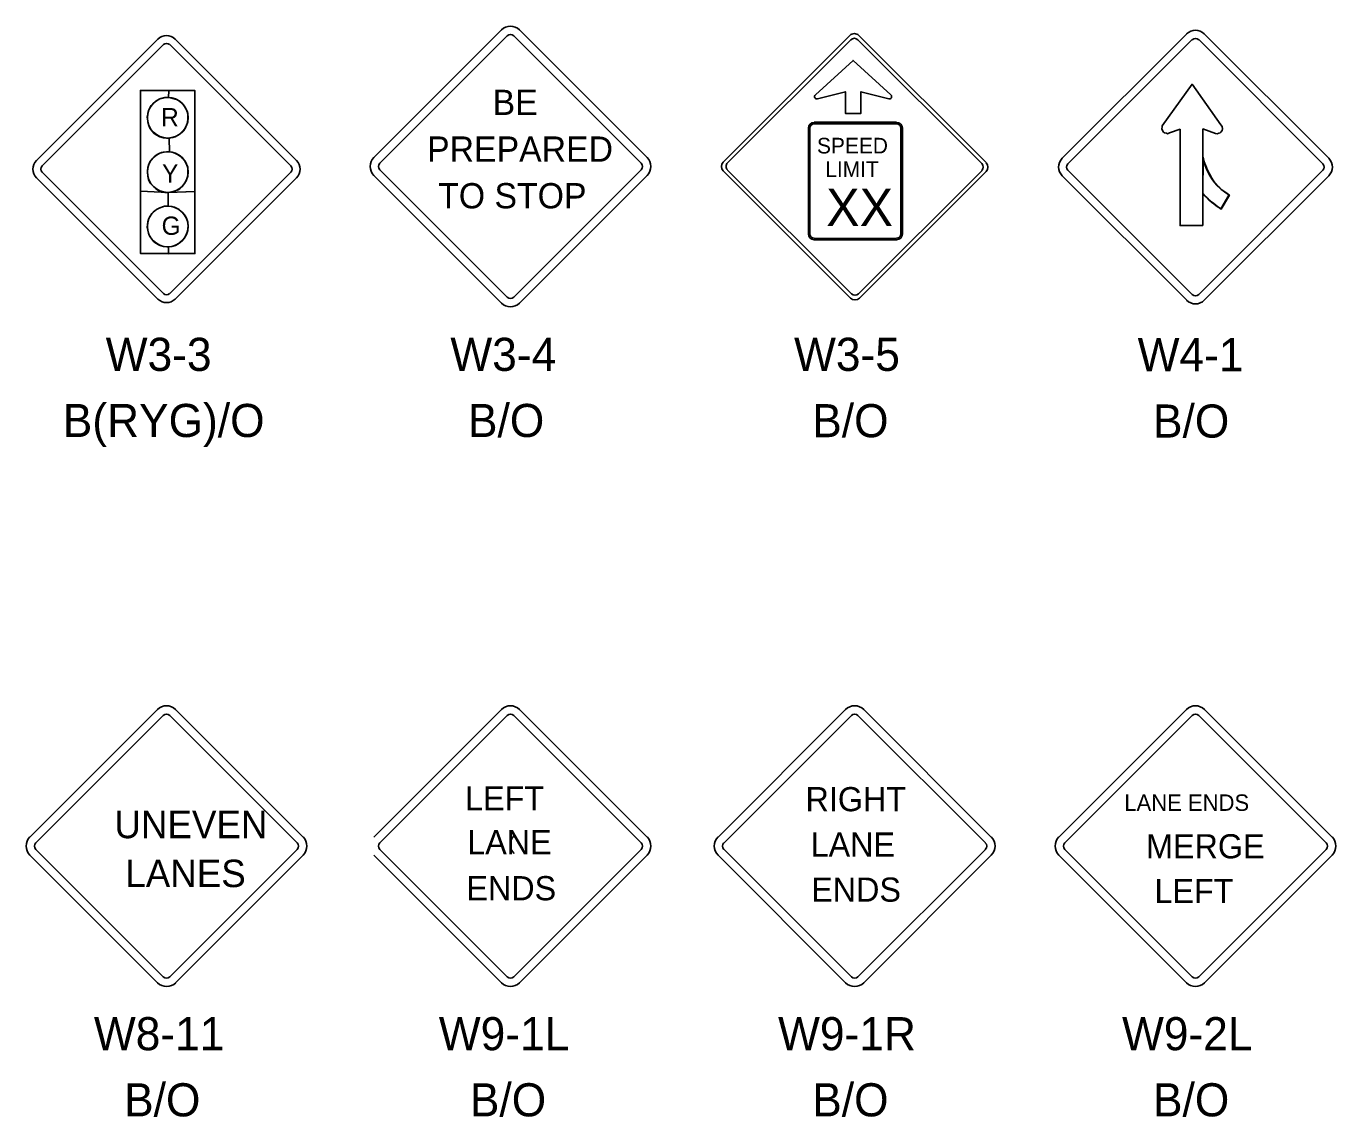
# Model space of a CAD drawing. Extents: x 10034 to 10794, y 10044 to 10499.
# Drawn here: x 10034.9 to 10173.2, y 10279.6 to 10394.8 of the extents above; entities that cross this region are included whole.
import ezdxf

# ---------------------------------------------------------------- set-up
doc = ezdxf.new("R2010")
doc.units = 0
for name, color, linetype in [('DSIndex', 7, 'Continuous'), ('DSText', 7, 'Continuous'), ('DSTitle', 7, 'Continuous'), ('PlotBorder_dp', 7, 'Continuous')]:
    doc.layers.add(name, color=color, linetype=linetype)

msp = doc.modelspace()

# ---------------------------------------------------------------- linework, layer by layer
at = {"layer": 'DSIndex'}
for p, q in [((10071.58, 10380.96), (10085.06, 10394.44)), ((10072.21, 10380.35), (10085.67, 10393.81)), ((10086.37, 10393.81), (10099.82, 10380.35)), ((10086.98, 10394.44), (10100.45, 10380.96)), ((10108.5, 10380.47), (10121.88, 10393.86)), ((10136.27, 10380.41), (10122.82, 10393.86)), ((10144.31, 10380.87), (10157.46, 10394.02)), ((10159.32, 10394.02), (10172.47, 10380.87)), ((10035.94, 10380.64), (10048.77, 10393.47)), ((10036.54, 10380.06), (10049.35, 10392.88)), ((10050.02, 10392.88), (10062.83, 10380.06)), ((10050.6, 10393.47), (10063.42, 10380.64)), ((10108.96, 10380.38), (10121.98, 10393.4)), ((10135.81, 10380.31), (10122.73, 10393.4)), ((10144.92, 10380.28), (10158.05, 10393.41)), ((10158.73, 10393.41), (10171.86, 10380.28)), ((10046.94, 10388.03), (10052.68, 10388.03)), ((10046.94, 10370.8), (10046.94, 10388.03)), ((10052.68, 10388.03), (10052.68, 10370.8)), ((10118.47, 10387.15), (10118.47, 10387.15)), ((10118.47, 10387.15), (10118.47, 10387.15)), ((10118.47, 10387.15), (10118.47, 10387.15)), ((10117.49, 10384.05), (10117.49, 10372.88)), ((10117.65, 10384.05), (10117.65, 10372.88)), ((10126.81, 10384.68), (10118.11, 10384.68)), ((10126.81, 10384.52), (10118.11, 10384.52)), ((10127.27, 10372.88), (10127.27, 10384.05)), ((10127.43, 10372.88), (10127.43, 10384.05)), ((10048.77, 10365.99), (10035.94, 10378.82)), ((10049.35, 10366.59), (10036.54, 10379.4)), ((10062.83, 10379.4), (10050.02, 10366.59)), ((10063.42, 10378.82), (10050.6, 10365.99)), ((10085.06, 10365.57), (10071.58, 10379.05)), ((10085.67, 10366.2), (10072.21, 10379.66)), ((10099.82, 10379.66), (10086.37, 10366.2)), ((10100.45, 10379.05), (10086.98, 10365.57)), ((10121.95, 10366.09), (10108.5, 10379.54)), ((10122.04, 10366.55), (10108.96, 10379.63)), ((10122.79, 10366.55), (10135.81, 10379.56)), ((10122.88, 10366.09), (10136.27, 10379.47)), ((10157.46, 10365.86), (10144.31, 10379.01)), ((10158.05, 10366.47), (10144.92, 10379.6)), ((10171.86, 10379.6), (10158.73, 10366.47)), ((10172.47, 10379.01), (10159.32, 10365.86)), ((10161.08, 10375.54), (10161.93, 10376.96)), ((10118.11, 10372.41), (10126.81, 10372.41)), ((10118.11, 10372.25), (10126.81, 10372.25)), ((10052.68, 10370.8), (10046.94, 10370.8)), ((10035.25, 10309.13), (10048.73, 10322.61)), ((10035.88, 10308.52), (10049.34, 10321.98)), ((10050.03, 10321.98), (10063.49, 10308.52)), ((10050.64, 10322.61), (10064.12, 10309.13)), ((10049.34, 10294.37), (10035.88, 10307.83)), ((10063.49, 10307.83), (10050.03, 10294.37)), ((10048.73, 10293.74), (10035.25, 10307.22)), ((10064.12, 10307.22), (10050.64, 10293.74))]:
    msp.add_line(p, q, dxfattribs=at)
for points in [[(10118.23, 10387.58), (10122.22, 10391.21), (10126.21, 10387.58)], [(10118.23, 10387.58), (10122.22, 10391.21), (10126.21, 10387.58)], [(10118.23, 10387.58), (10122.22, 10391.21), (10126.21, 10387.58)], [(10125.98, 10387.15), (10123.05, 10387.9), (10123.05, 10385.62), (10121.4, 10385.62), (10121.4, 10387.9), (10118.47, 10387.15)], [(10125.98, 10387.15), (10123.05, 10387.9), (10123.05, 10385.62), (10121.4, 10385.62), (10121.4, 10387.9), (10118.47, 10387.15)], [(10125.98, 10387.15), (10123.05, 10387.9), (10123.05, 10385.62), (10121.4, 10385.62), (10121.4, 10387.9), (10118.47, 10387.15)]]:
    msp.add_lwpolyline(points, dxfattribs=at)
for points in [[(10049.92, 10388.04), (10049.88, 10387.31), (10049.69, 10387.31), (10049.49, 10387.28), (10049.29, 10387.21), (10049.09, 10387.18), (10048.89, 10387.11), (10048.72, 10387.01), (10048.56, 10386.91), (10048.46, 10386.81), (10048.29, 10386.71), (10048.19, 10386.58), (10048.06, 10386.45), (10047.96, 10386.28), (10047.86, 10386.08), (10047.76, 10385.92), (10047.73, 10385.72), (10047.69, 10385.55), (10047.63, 10385.25), (10047.66, 10384.99), (10047.73, 10384.62), (10047.83, 10384.35), (10047.93, 10384.06), (10048.12, 10383.79), (10048.36, 10383.49), (10048.66, 10383.33), (10048.99, 10383.13), (10049.35, 10383.03), (10049.69, 10382.99), (10049.95, 10382.99), (10049.98, 10381.57), (10049.69, 10381.57), (10049.42, 10381.53), (10049.15, 10381.47), (10048.89, 10381.37), (10048.69, 10381.27), (10048.46, 10381.1), (10048.23, 10380.9), (10048.09, 10380.7), (10047.93, 10380.5), (10047.83, 10380.2), (10047.69, 10379.91), (10047.66, 10379.51), (10047.69, 10379.01), (10047.79, 10378.58), (10047.96, 10378.25), (10048.23, 10377.95), (10048.56, 10377.65), (10048.82, 10377.45), (10049.19, 10377.32), (10049.52, 10377.25), (10049.82, 10377.25), (10046.93, 10377.38), (10046.93, 10388.04)], [(10049.92, 10388.02), (10049.89, 10387.3), (10050.25, 10387.24), (10050.61, 10387.12), (10050.85, 10387.04), (10051.08, 10386.86), (10051.3, 10386.71), (10051.47, 10386.53), (10051.62, 10386.32), (10051.74, 10386.05), (10051.89, 10385.75), (10051.95, 10385.39), (10051.95, 10385.04), (10051.89, 10384.64), (10051.8, 10384.38), (10051.68, 10384.08), (10051.5, 10383.81), (10051.26, 10383.6), (10051.12, 10383.45), (10050.85, 10383.27), (10050.61, 10383.15), (10050.34, 10383.07), (10050.13, 10383.03), (10049.95, 10383), (10049.98, 10381.57), (10050.28, 10381.51), (10050.55, 10381.42), (10050.76, 10381.3), (10051.03, 10381.15), (10051.26, 10381), (10051.41, 10380.83), (10051.65, 10380.56), (10051.8, 10380.26), (10051.92, 10379.93), (10051.95, 10379.57), (10051.92, 10379.12), (10051.86, 10378.8), (10051.77, 10378.5), (10051.62, 10378.26), (10051.44, 10378.02), (10051.3, 10377.84), (10051.08, 10377.66), (10050.91, 10377.54), (10050.61, 10377.42), (10050.31, 10377.3), (10049.89, 10377.24), (10052.67, 10377.36), (10052.68, 10388.03)], [(10159.17, 10373.78), (10159.17, 10383.97), (10160.51, 10383.49), (10160.67, 10383.46), (10160.85, 10383.51), (10160.98, 10383.55), (10161.07, 10383.64), (10161.21, 10383.82), (10161.25, 10384), (10161.21, 10384.22), (10161.08, 10384.42), (10158.03, 10388.7), (10154.88, 10384.29), (10154.86, 10384.18), (10154.82, 10384), (10154.91, 10383.82), (10155, 10383.64), (10155.13, 10383.55), (10155.31, 10383.51), (10155.44, 10383.46), (10155.65, 10383.56), (10156.76, 10383.94), (10156.76, 10373.75)], [(10161.12, 10375.51), (10161.98, 10376.97), (10161.6, 10377.24), (10161.1, 10377.57), (10160.97, 10377.7), (10160.65, 10378.04), (10160.4, 10378.32), (10160.13, 10378.76), (10159.86, 10379.24), (10159.65, 10379.62), (10159.48, 10380.06), (10159.31, 10380.51), (10159.2, 10380.99), (10159.18, 10377.14), (10159.38, 10376.94), (10159.68, 10376.6), (10159.98, 10376.35), (10160.3, 10376.12), (10160.58, 10375.89)], [(10049.84, 10377.25), (10049.84, 10375.82), (10049.48, 10375.8), (10049.17, 10375.71), (10048.89, 10375.61), (10048.7, 10375.5), (10048.47, 10375.37), (10048.28, 10375.19), (10048.12, 10375.02), (10048.01, 10374.87), (10047.88, 10374.64), (10047.78, 10374.41), (10047.7, 10374.16), (10047.67, 10373.88), (10047.65, 10373.57), (10047.69, 10373.29), (10047.78, 10372.96), (10047.89, 10372.68), (10048.12, 10372.31), (10048.35, 10372.05), (10048.62, 10371.86), (10048.85, 10371.72), (10049.13, 10371.61), (10049.42, 10371.55), (10049.71, 10371.51), (10049.9, 10371.51), (10049.9, 10370.79), (10046.94, 10370.8), (10046.94, 10377.38)], [(10049.84, 10377.25), (10049.84, 10375.82), (10050.18, 10375.78), (10050.51, 10375.69), (10050.79, 10375.57), (10051, 10375.44), (10051.21, 10375.29), (10051.4, 10375.1), (10051.58, 10374.89), (10051.71, 10374.68), (10051.82, 10374.45), (10051.9, 10374.22), (10051.94, 10373.99), (10051.96, 10373.72), (10051.94, 10373.42), (10051.9, 10373.17), (10051.8, 10372.9), (10051.69, 10372.64), (10051.56, 10372.41), (10051.34, 10372.18), (10051.14, 10371.99), (10050.89, 10371.8), (10050.62, 10371.67), (10050.26, 10371.55), (10049.96, 10371.51), (10049.9, 10371.51), (10049.9, 10370.79), (10052.68, 10370.8), (10052.66, 10377.37)]]:
    msp.add_lwpolyline(points, close=True, dxfattribs=at)
for centre in [(10049.81, 10385.16), (10049.81, 10379.42), (10049.81, 10373.67)]:
    msp.add_circle(centre, 2.15, dxfattribs=at)
for centre, radius, start, end in [((10049.68, 10392.56), 1.29, 45, 135), ((10086.02, 10393.48), 1.36, 45, 135), ((10086.02, 10393.47), 0.49, 45, 135), ((10122.35, 10393.39), 0.662, 44.9995, 135.0006), ((10122.35, 10393.02), 0.53, 45, 134.9881), ((10158.39, 10393.08), 1.32, 45, 135), ((10158.39, 10393.07), 0.478, 45, 135), ((10049.68, 10392.55), 0.467, 45, 135), ((10118.4, 10387.39), 0.25, 132.3048, 284.4075), ((10118.4, 10387.39), 0.25, 132.3048, 284.4075), ((10118.4, 10387.39), 0.25, 132.3048, 284.4075), ((10126.04, 10387.39), 0.25, 255.5925, 47.6952), ((10126.04, 10387.39), 0.25, 255.5925, 47.6952), ((10126.04, 10387.39), 0.25, 255.5925, 47.6952), ((10118.11, 10384.05), 0.621, 90, 180), ((10118.11, 10384.05), 0.466, 90, 180), ((10126.81, 10384.05), 0.621, 0, 90), ((10126.81, 10384.05), 0.466, 0, 90), ((10164.94, 10382), 5.84, 189.3059, 239.5225), ((10036.86, 10379.73), 1.29, 135, 225), ((10036.87, 10379.73), 0.467, 135, 225), ((10062.5, 10379.73), 0.467, 315, 45), ((10062.51, 10379.73), 1.29, 315, 45), ((10072.55, 10380.01), 1.36, 135, 225), ((10072.56, 10380.01), 0.49, 135, 225), ((10099.48, 10380.01), 0.49, 315, 45), ((10099.49, 10380.01), 1.36, 315, 45), ((10108.97, 10380.01), 0.662, 135.0005, 225), ((10109.33, 10380.01), 0.53, 134.9879, 225), ((10135.43, 10379.94), 0.53, 315, 45), ((10135.8, 10379.94), 0.662, 315, 44.9995), ((10145.25, 10379.94), 1.32, 135, 225), ((10145.25, 10379.94), 0.478, 135, 225), ((10171.52, 10379.94), 0.478, 315, 45), ((10171.53, 10379.94), 1.32, 315, 45), ((10164.94, 10382), 7.53, 220.0501, 239.5225), ((10118.11, 10372.88), 0.621, 180, 270), ((10118.11, 10372.88), 0.466, 180, 270), ((10126.81, 10372.88), 0.466, 270, 0), ((10126.81, 10372.88), 0.621, 270, 0), ((10049.69, 10366.91), 1.29, 225, 315), ((10049.68, 10366.92), 0.467, 225, 315), ((10086.02, 10366.55), 0.49, 225, 315), ((10122.42, 10366.56), 0.662, 225, 315), ((10122.42, 10366.92), 0.53, 225, 315), ((10158.39, 10366.8), 1.32, 225, 315), ((10158.39, 10366.81), 0.478, 225, 315), ((10086.02, 10366.53), 1.36, 225, 315), ((10049.68, 10321.65), 1.36, 45, 135), ((10049.68, 10321.64), 0.49, 45, 135), ((10036.21, 10308.18), 1.36, 135, 225), ((10063.15, 10308.18), 1.36, 315, 45), ((10036.22, 10308.18), 0.49, 135, 225), ((10063.14, 10308.18), 0.49, 315, 45), ((10049.68, 10294.71), 0.49, 225, 315), ((10049.69, 10294.7), 1.36, 225, 315)]:
    msp.add_arc(centre, radius, start, end, dxfattribs=at)
at = {"layer": 'DSText'}
for p, q in [((10071.59, 10309.13), (10085.06, 10322.61)), ((10086.98, 10322.61), (10100.45, 10309.13)), ((10107.95, 10309.13), (10121.43, 10322.61)), ((10123.34, 10322.61), (10136.82, 10309.13)), ((10143.96, 10309.13), (10157.43, 10322.61)), ((10159.35, 10322.61), (10172.82, 10309.13)), ((10085.06, 10293.74), (10071.59, 10307.22)), ((10100.45, 10307.22), (10086.98, 10293.74)), ((10121.43, 10293.74), (10107.95, 10307.22)), ((10136.82, 10307.22), (10123.34, 10293.74)), ((10157.43, 10293.74), (10143.96, 10307.22)), ((10172.82, 10307.22), (10159.35, 10293.74))]:
    msp.add_line(p, q, dxfattribs=at)
for centre, start, end in [((10086.02, 10321.65), 45, 135), ((10122.38, 10321.65), 45, 135), ((10158.39, 10321.65), 45, 135), ((10087.37, 10308.34), 135, 225), ((10099.49, 10308.18), 315, 45), ((10108.91, 10308.18), 135, 225), ((10135.85, 10308.18), 315, 45), ((10144.92, 10308.18), 135, 225), ((10171.86, 10308.18), 315, 45), ((10086.02, 10294.7), 225, 315), ((10122.39, 10294.7), 225, 315), ((10158.39, 10294.7), 225, 315)]:
    msp.add_arc(centre, 1.36, start, end, dxfattribs=at)
at = {"layer": 'DSTitle'}
for p, q in [((10072.21, 10308.52), (10085.67, 10321.98)), ((10086.37, 10321.98), (10099.83, 10308.52)), ((10108.58, 10308.52), (10122.04, 10321.98)), ((10122.73, 10321.98), (10136.19, 10308.52)), ((10144.58, 10308.52), (10158.04, 10321.98)), ((10158.74, 10321.98), (10172.2, 10308.52)), ((10085.67, 10294.37), (10072.21, 10307.83)), ((10099.83, 10307.83), (10086.37, 10294.37)), ((10122.04, 10294.37), (10108.58, 10307.83)), ((10136.19, 10307.83), (10122.73, 10294.37)), ((10158.04, 10294.37), (10144.58, 10307.83)), ((10172.2, 10307.83), (10158.74, 10294.37))]:
    msp.add_line(p, q, dxfattribs=at)
for centre, start, end in [((10086.02, 10321.64), 45, 135), ((10122.38, 10321.64), 45, 135), ((10158.39, 10321.64), 45, 135), ((10072.56, 10308.18), 135, 225), ((10099.48, 10308.18), 315, 45), ((10108.92, 10308.18), 135, 225), ((10135.84, 10308.18), 315, 45), ((10144.93, 10308.18), 135, 225), ((10171.85, 10308.18), 315, 45), ((10086.02, 10294.72), 225, 315), ((10122.38, 10294.72), 225, 315), ((10158.39, 10294.72), 225, 315)]:
    msp.add_arc(centre, 0.49, start, end, dxfattribs=at)

# ---------------------------------------------------------------- texts
at = {"layer": 'DSIndex'}
for s, height, p in [('BE', 2.67, (10084.13, 10385.45)), ('R', 1.93, (10049.11, 10384.25)), ('PREPARED', 2.67, (10077.21, 10380.51)), ('SPEED', 1.654, (10118.4, 10381.38)), ('Y', 1.93, (10049.21, 10378.31)), ('LIMIT', 1.654, (10119.28, 10378.89)), ('TO STOP', 2.67, (10078.38, 10375.58)), ('XX', 3.963, (10119.37, 10373.7)), ('G', 1.93, (10049.16, 10372.78)), ('W3-3', 3.5, (10043.26, 10358.4)), ('W3-4', 3.5, (10079.67, 10358.4)), ('W3-5', 3.5, (10115.98, 10358.4)), ('W4-1', 3.5, (10152.28, 10358.36)), ('B(RYG)/O', 3.5, (10038.72, 10351.41)), ('B/O', 3.5, (10081.53, 10351.41)), ('B/O', 3.5, (10117.9, 10351.39)), ('B/O', 3.5, (10153.9, 10351.35)), ('UNEVEN', 2.901, (10044.18, 10309.01)), ('LANES', 2.901, (10045.33, 10303.84)), ('W8-11', 3.5, (10042.01, 10286.6)), ('B/O', 3.5, (10045.2, 10279.61))]:
    msp.add_text(s, height=height, dxfattribs=at).set_placement(p)
at = {"layer": 'PlotBorder_dp'}
for s, height, p in [('LEFT', 2.553, (10081.22, 10311.95)), ('RIGHT', 2.553, (10117.19, 10311.86)), ('LANE ENDS', 1.74, (10150.87, 10311.9)), ('LANE', 2.553, (10081.45, 10307.32)), ('LANE', 2.553, (10117.73, 10307.06)), ('MERGE', 2.553, (10153.17, 10306.88)), ('ENDS', 2.553, (10081.36, 10302.45)), ('ENDS', 2.553, (10117.79, 10302.3)), ('LEFT', 2.553, (10154.06, 10302.15)), ('W9-1L', 3.5, (10078.45, 10286.6)), ('W9-1R', 3.5, (10114.29, 10286.6)), ('W9-2L', 3.5, (10150.63, 10286.6)), ('B/O', 3.5, (10081.73, 10279.61)), ('B/O', 3.5, (10117.9, 10279.61)), ('B/O', 3.5, (10153.9, 10279.61))]:
    msp.add_text(s, height=height, dxfattribs=at).set_placement(p)

doc.saveas('drawing.dxf')
